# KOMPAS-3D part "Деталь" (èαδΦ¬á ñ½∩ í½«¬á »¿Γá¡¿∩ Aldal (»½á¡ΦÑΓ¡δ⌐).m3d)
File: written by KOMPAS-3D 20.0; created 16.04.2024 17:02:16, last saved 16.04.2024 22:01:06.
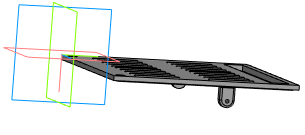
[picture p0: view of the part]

Document properties: Полное имя файла: D:\Soft 4 pads\Чертежи корпусов и т.д\Крышка для блока питания Aldal (планшетный).m3d

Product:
- Part/product: Деталь
    Масса: 0.214011

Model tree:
1. Эскиз:1
2. Элемент выдавливания:1
     Расстояние 1 = 2.5
3. Эскиз:2  (with: Элемент выдавливания:1)
4. Элемент выдавливания:2
     Расстояние 1 = 0.5
5. Эскиз:3  (with: Элемент выдавливания:2)
6. Элемент выдавливания:3
     Расстояние 2 = 10
7. Скругление:1  (with: Элемент выдавливания:3)
     Радиус = 1
8. Скругление:2  (with: Элемент выдавливания:3)
     Радиус = 1
9. Эскиз:4  (with: Элемент выдавливания:2)
10. Элемент выдавливания:4
     Расстояние 1 = 11
11. Эскиз:5  (with: Элемент выдавливания:2)
12. Элемент выдавливания:5
     Расстояние 2 = 150
13. Скругление:5  (with: Элемент выдавливания:4)
     Радиус = 4
14. Скругление:6  (with: Элемент выдавливания:4)
     Радиус = 4
15. Скругление:7  (with: Элемент выдавливания:4)
     Радиус = 4
16. Скругление:8  (with: Элемент выдавливания:4)
     Радиус = 4
17. Эскиз:6  (with: Элемент выдавливания:2, Элемент выдавливания:4)
18. Элемент выдавливания:6
     Расстояние 1 = 16
19. Скругление:9  (with: Элемент выдавливания:6)
     Радиус = 1
20. Скругление:11  (with: Элемент выдавливания:6)
     Радиус = 1
21. Эскиз:7  (with: Элемент выдавливания:2)
22. Элемент выдавливания:7
     Расстояние 2 = 4
23. Эскиз:8  (with: Элемент выдавливания:1)
24. Элемент выдавливания:8
     Расстояние 2 = 10
25. Эскиз:9  (with: Элемент выдавливания:2, Элемент выдавливания:4)
26. Скругление:12  (with: Элемент выдавливания:6)
     Радиус = 1
27. Скругление:13  (with: Элемент выдавливания:6)
     Радиус = 1
28. Эскиз:10  (with: Элемент выдавливания:2, Элемент выдавливания:4, Элемент выдавливания:7)
29. Элемент выдавливания:9
     Расстояние 2 = 10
